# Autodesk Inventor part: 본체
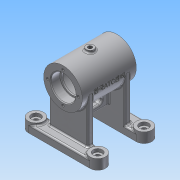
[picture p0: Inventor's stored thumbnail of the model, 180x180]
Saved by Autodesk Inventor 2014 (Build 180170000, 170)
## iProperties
Created: 2015-11
Part Number: 본체
Material: 알루미늄 6061
Document SubType Name: Modeling
Designer: 103-08
Density: 2.71 g/cm^3
Appearance: 알루미늄 - 평지
Mass: 358.948 g
Surface Area: 460.354 cm^2
Volume: 132.453 cm^3
Author: 103-08
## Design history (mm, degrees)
sketch "스케치1"
  geometry: L1 (-40, 40)-(40, 40); L2 (40, 20)-(-40, 20); L3 (-40, -20)-(40, -20); L4 (0, 20)-(0, -8.942); L5 (-40, -40)-(40, -40); A1 r 10 centre (-40, 30) between (-40, 40) and (-40, 20); A2 r 10 centre (40, 30) between (40, 40) and (40, 20); A3 r 10 centre (-40, -30) between (-40, -20) and (-40, -40); A4 r 10 centre (40, -30) between (40, -20) and (40, -40); 1 further point
  constraints: 10 end point, 8 point on circle, 5 tangent, 4 centre point, 3 equal radius, 3 vertical alignment, 2 horizontal alignment, 1 midpoint, 1 parallel, 1 perpendicular
  dimensions: "d2" = 20 diameter of A1; "d3" = 80 distance of A2.centre A1.centre; "d6" = 80 distance of L1.start L1.end; "d7" = 80 distance of L5.start L5.end; "d28" = 40 distance from line of point (0, 0) L1; "d29" = 40 distance from line of point (0, 0) L5
extrude "돌출1" new body sketch "스케치1" distance "d8" = 10; taper "d9" = 0 deg
sketch "스케치4"
  geometry: L1 (-35, 68)-(35, 68); L2 (-35, 84)-(-35, 93); L3 (-35, 93)-(35, 93); L4 (35, 93)-(35, 84); L5 (35, 84)-(23, 84); L6 (23, 84)-(23, 82); L7 (23, 82)-(21, 82); L8 (21, 82)-(21, 89); L9 (21, 89)-(-21, 89); L10 (-21, 89)-(-21, 82); L11 (-21, 82)-(-23, 82); L12 (-23, 82)-(-23, 84); L13 (-23, 84)-(-35, 84); 2 further points
  constraints: 26 end point, 10 parallel, 4 collinear, 2 perpendicular, 2 point on line, 1 horizontal, 1 midpoint, 1 vertical alignment
  dimensions: "d17" = 68 vertical distance of point (0, 0) L1.end; "d18" = 70 distance of L1.start L1.end; "d19" = 12 distance of L12.end L2.start; "d20" = 2 distance of L10.end L11.end; "d21" = 32 diameter of L13 L1; "d22" = 50 diameter of L3 L1; "d23" = 42 diameter of L9 L1; "d24" = 28 diameter of L11 L1
revolve "회전1" sketch "스케치4" stored, may be unused: angle "d25" = 90 deg
sketch "스케치7"
  geometry: L1 (80, -10)-(0, -10) reference; L2 (65, -68)-(65, -10); L3 (15, -68)-(15, -10); A1 r 25 centre (40, -68) between (65, -68) and (15, -68) reference; 1 further point
  constraints: 4 end point, 2 perpendicular, 2 point on circle, 2 point on line, 2 tangent
extrude "돌출2" join sketch "스케치7" distance "d30" = 8; taper "d31" = 0 deg
node "작업 평면2"
sketch "스케치8"
  geometry: C1 r 5 at (0, 0); 1 further point
  constraints: 1 centre point, 1 coincident
  dimensions: "d33" = 10 diameter of C1
extrude "돌출3" join sketch "스케치8" stored distance "d34" = 8; taper "d35" = 0 deg
sketch "스케치9"
  geometry: L1 (0, 0)-(0, 33.311); L2 (0, 0)-(-12.5, 21.651); C1 r 16 at (0, 0) reference; 1 further point
  constraints: 4 end point, 1 vertical, 2 other
  dimensions: "d36" = 30 deg angle of L1 L2
node "작업 평면4"
  node "작업 평면3"
sketch "스케치11"
  geometry: C1 r 6 at (35, 0); 2 further points
  constraints: 1 centre point, 1 horizontal alignment, 1 vertical alignment
  dimensions: "d38" = 12 diameter of C1
extrude "돌출4" join sketch "스케치11" stored distance "d39" = 8; taper "d40" = 0 deg
node "작업 평면6"
sketch "스케치12"
  geometry: L1 (-20, 68)-(-20, 10) reference; L2 (20, 68)-(20, 10) reference; L3 (-20, 23)-(20, 23); L4 (-35, 43)-(35, 43) reference; L5 (-20, 23)-(-20, 43); L6 (20, 43)-(20, 23); L7 (-20, 43)-(-20, 44.75); L8 (20, 44.75)-(20, 43); L9 (20, 44.75)-(-20, 44.75); 1 further point
  constraints: 12 end point, 8 point on line, 2 collinear, 2 perpendicular
  dimensions: "d42" = 20 distance between parallel lines of L3 L4; "d45" = 1.75028 distance between parallel lines of L9 L4
extrude "돌출5" join sketch "스케치12" stored distance "d43" = 8; taper "d44" = 0 deg
sketch "스케치13"
  geometry: L1 (43.322, -20)-(23, -20) reference; L2 (29.5, -8)-(29.5, 8); L3 (36.5, 8)-(36.5, -8); L4 (0, 20)-(10, 20) reference; L5 (0, -20)-(10, -20) reference; L6 (96, 5)-(96, -5) reference; L7 (96, 0)-(10, 0); A1 r 3.5 centre (33, 8) between (36.5, 8) and (29.5, 8); A2 r 3.5 centre (33, -8) between (29.5, -8) and (36.5, -8); 1 further point
  constraints: 6 end point, 4 point on circle, 4 tangent, 2 centre point, 2 perpendicular, 1 equal radius, 1 midpoint
  dimensions: "d48" = 3.5 radius of A2; "d49" = 33 horizontal distance of A2.centre point (0, 0); "d50" = 11.5 dimension on A1 L7; "d51" = 11.5 dimension on A2 L7
extrude "돌출6" cut sketch "스케치13" stored distance "d52" = 8; taper "d53" = 0 deg
node "작업 평면7"
sketch "스케치14"
  geometry: L1 (-5, 28)-(5, 28) reference; L2 (-35, -25)-(-35, 25) reference; L3 (-35, 25)-(35, 25) reference; 2 further points
  constraints: 1 other
  dimensions: "d54" = 35 distance from line of point (0, 0) L2; "d104" = 25 distance from line of L3 point (0, 0)
feature "엠보싱1" sketch "스케치14" dims "d2" = 20, "d3" = 80, "d6" = 80, "d7" = 80, "d28" = 40, "d29" = 40, "d56" = 0.5, "d57" = 0
sketch "스케치15"
  geometry: C1 r 16 at (0, 0) reference; C2 r 25 at (0, 0) reference; A1 r 20 centre (0, 0) between (0, 20) and (-20, 0); 3 further points
  constraints: 4 point on circle, 2 horizontal alignment, 2 vertical alignment, 1 centre point, 1 coincident
  dimensions: "d58" = 40 diameter of A1
hole "구멍1" sketch "스케치15" at (0, 20), (-20, 0), (20, 0), (0, -20) diameter "d59" = 3.242; stored, may be unused: countersink angle "d63" = 90 deg, drill point angle "d65" = 118 deg; dims "d60" = 8, "d61" = 4, "d62" = 2, "d64" = 10
sketch "스케치16"
  geometry: L1 (40, 40)-(-40, 40) reference; C1 r 10 at (-40, 30); C2 r 10 at (40, 30); A1 r 10 centre (40, 30) between (40, 20) and (40, 40) reference; A2 r 10 centre (-40, 30) between (-40, 40) and (-40, 20) reference; 1 further point
  constraints: 2 centre point, 2 coincident, 1 tangent
  dimensions: "d66" = 20 diameter of C1
extrude "돌출7" join sketch "스케치16" distance "d67" = 3; taper "d68" = 0 deg
hole "구멍2" diameter "d71" = 6; stored, may be unused: countersink angle "d75" = 90 deg, drill point angle "d77" = 0 deg; dims "d69" = 10, "d70" = 10, "d72" = 8, "d73" = 12, "d74" = 4, "d76" = 10
fillet "모깎기1" dims "d78" = 0.3, "d79" = 3
fillet "모깎기2" dims "d80" = 2
fillet "모깎기3" dims "d81" = 2
hole "구멍3" diameter "d84" = 5.188; stored, may be unused: countersink angle "d88" = 90 deg, drill point angle "d90" = 0 deg; dims "d82" = 10, "d83" = 10, "d85" = 8, "d86" = 12, "d87" = 4, "d89" = 10
hole "구멍4" diameter "d93" = 5.188; stored, may be unused: countersink angle "d97" = 90 deg, drill point angle "d99" = 0 deg; dims "d91" = 10, "d92" = 10, "d94" = 8, "d95" = 12, "d96" = 4, "d98" = 10
chamfer "모따기1" distance "d100" = 1; stored, may be unused: second distance "d101" = 2, angle "d102" = 45 deg
fillet "모깎기4" dims "d103" = 2
node "솔리드1"
mirror "대칭1"
mirror "대칭2"
mirror "대칭3"
mirror "대칭4"
other parameters: "d32" = 96, "d37" = 3, "d41" = 0
